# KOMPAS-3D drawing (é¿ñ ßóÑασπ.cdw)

Referenced files in /: h8, d11, p6, k6
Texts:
  ПЛК.303120.00.00 СБ
  Ревин ЕЕ
  Лит-Масса-Масштаб
  Материал-Предприятие
  ACAD_ISO10W100_RGB_255_128_0_SC_1_THICK_0.15
  ACAD_ISO10W100_RGB_51_51_51_SC_1_THICK_0.15
  ACAD_ISO10W100_RGB_255_128_0_SC_0.5_THICK_0.15
  ACAD_ISO10W100_RGB_255_64_0_SC_1_THICK_0.15
  ACAD_ISO08W100_RGB_255_64_0_SC_1_THICK_0.15
  ACAD_ISO03W100_RGB_0_0_0_SC_0.3_THICK_0.15
  ACAD_ISO10W100_RGB_255_63_0_SC_1_THICK_0.15
  ACAD_ISO10W100_RGB_255_63_0_SC_0.25_THICK_0.15
  ACAD_ISO10W100_RGB_255_63_0_SC_0.5_THICK_0.15
  gost6_RGB_255_128_0_SC_1_THICK_0.15
  ACAD_ISO10W100_RGB_51_51_51_SC_1_THICK_0.18
  ACAD_ISO10W100_RGB_0_0_0_SC_1_THICK_0.18
  gost6_RGB_255_128_0_SC_0.5_THICK_0.15
  ACAD_ISO10W100_RGB_51_51_51_SC_0.1_THICK_0.25
  POLYLINE_STYLE_0.18_RGB_0_0_255
  ACAD_ISO10W100_RGB_255_128_0_SC_0.75_THICK_0.15
  ACAD_ISO03W100_RGB_0_0_255_SC_0.25_THICK_0.5
  ACAD_ISO03W100_RGB_0_0_0_SC_0.1_THICK_0.15
  ACAD_ISO10W100_RGB_255_128_0_SC_1_THICK_0.18
  ACAD_ISO10W100_RGB_51_51_51_SC_1_THICK_0.25
  ACAD_ISO10W100_RGB_0_0_255_SC_0.5_THICK_0.15
  СONTINUOUS_RGB_0_0_0_THICK_0.5
  ACAD_ISO10W100_RGB_255_128_0_SC_0.25_THICK_0.15
  ACAD_ISO10W100_RGB_255_64_0_SC_1_THICK_0.18
  Стили документа
  Подшипник 36207K ГОСТ 831-75
  Подшипник
  ГОСТ
  Подшипник 7212А ГОСТ 27365-87
  Подшипник207 ГОСТ 8338-75
  Подшипник209 ГОСТ 8338-75
  Манжета
  Шайба 8 Л БрКМц3-1 ГОСТ 6402-70
  Шайба пружинная
  Шайба
  БрКМц3-1
  БрКМц3-1 ГОСТ 18175-78
  Болт М8-6g x 22.109.30ХГСА ГОСТ 7808-70
  Болт
  .30ХГСА
  Сталь 30ХГСА ГОСТ 4543-71
  ANSI37
  Редуктор цилиндрический
  двухступенчатый
  Сборочный чертеж
  Семенов А.М.
  РЦО.112.00.00 СБ-
  НИТПУ, ИДО,
  группа з-4681
Dimensions and other numbers on the sheet: 32; 72; 35; 70; 50; 90; 75; 65; 125; 3; 4; 5; 6; 7; 10; 11; 12; 13; 14; 16; 17; 18; 19; 20; 21; 28; 29; 36; 38; 39; 40; 41; 42; 43; 44; 45; 46; 47; 2; 55; 029; -6g; 1:1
